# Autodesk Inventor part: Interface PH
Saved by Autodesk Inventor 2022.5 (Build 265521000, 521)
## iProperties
Created: 2024-12
Part Number: Interface PH
Material: Generic
Document SubType Name: Modeling
Designer: AdminForWorker
Density: 1 g/cm^3
Appearance: Default
Title: Interface PH v1
Author: AdminForWorker
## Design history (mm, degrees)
feature "Body1"
body "Solid1"
